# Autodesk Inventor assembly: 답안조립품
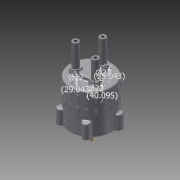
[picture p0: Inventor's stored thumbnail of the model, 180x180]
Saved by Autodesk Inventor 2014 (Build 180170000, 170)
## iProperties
Created: 2016-01
Part Number: 답안조립품
Document SubType Name: Assembly
Designer: Administrator
Mass: 2145.78 g
Surface Area: 1791.59 cm^2
Volume: 441.313 cm^3
Density: 4.86225 g/cm^3
Author: Administrator
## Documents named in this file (14)
- C:\Users\Administrator\Desktop\360106V1037\답안조립품.iam
- C:\Users\Administrator\Desktop\360106V1037\M5x0.8x20.ipt
- C:\Users\Administrator\Desktop\360106V1037\멈춤링 10 x 1.ipt
- C:\Users\Administrator\Desktop\360106V1037\멈춤링 22 x 1.2.ipt
- C:\Users\Administrator\Desktop\360106V1037\메인 축.ipt
- C:\Users\Administrator\Desktop\360106V1037\베어링 NA 4900.ipt
- C:\Users\Administrator\Desktop\360106V1037\본체.ipt
- C:\Users\Administrator\Desktop\360106V1037\슬라이드 축.ipt
- C:\Users\Administrator\Desktop\360106V1037\오일실.ipt
- C:\Users\Administrator\Desktop\360106V1037\커버.ipt
- C:\Users\Administrator\Desktop\360106V1037\판캠.ipt
- C:\Users\Administrator\Desktop\360106V1037\가변스프링 11.ipt
- C:\Users\Administrator\Desktop\360106V1037\가변스프링 12.ipt
- C:\Users\Administrator\Desktop\360106V1037\가변스프링 13.ipt
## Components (8 placed, 4 different names)
1. 가변스프링 11:1
2. 가변스프링 12:1
3. 가변스프링 13:1
4. M5x0.8x20:1
5. M5x0.8x20:2
6. M5x0.8x20:3
7. M5x0.8x20:4
8. M5x0.8x20:5
